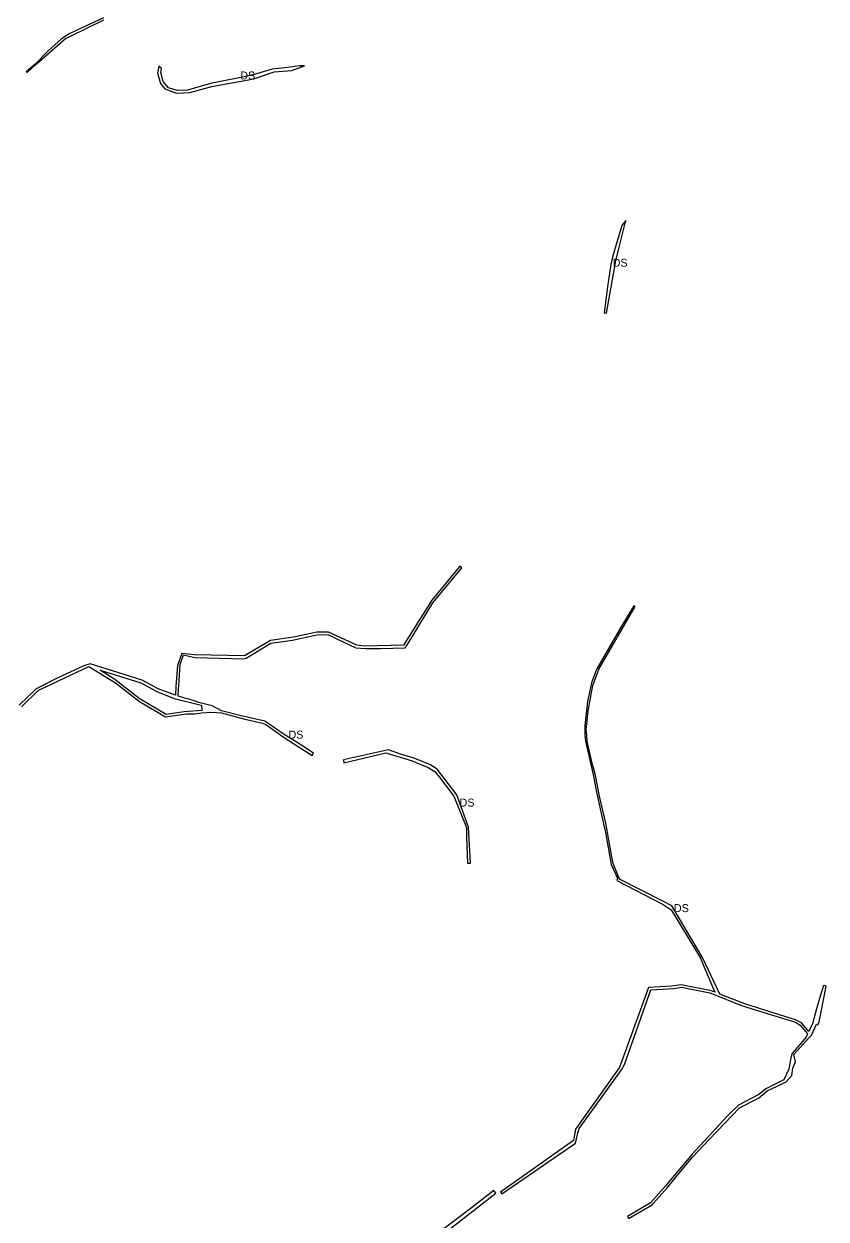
# Model space of a CAD drawing. Extents: x -477304 to -465641, y -1159113 to -1149285.
# Drawn here: x -475036 to -474134, y -1152941 to -1151597 of the extents above; entities that cross this region are included whole.
import ezdxf

# ---------------------------------------------------------------- set-up
doc = ezdxf.new("R2010")
doc.units = 0
doc.layers.add('35', color=7, linetype='Continuous')

msp = doc.modelspace()

# ---------------------------------------------------------------- linework, layer by layer
at = {"layer": '35'}
for p, q in [((-474985.6, -1151608.3), (-474994, -1151613.9)), ((-475023.8, -1151642.3), (-475033.9, -1151651.1)), ((-474881.6, -1151647.1), (-474884.7, -1151644.6)), ((-474882.5, -1151651.8), (-474881.6, -1151647.1)), ((-475033.9, -1151651.1), (-475032.5, -1151651.4)), ((-474757, -1151648), (-474781, -1151655.2)), ((-474878.1, -1151670), (-474864.7, -1151675.1)), ((-474849.7, -1151674.4), (-474825.2, -1151667.5)), ((-474864.7, -1151675.1), (-474849.7, -1151674.4)), ((-474359.3, -1151818.1), (-474363.9, -1151823.9)), ((-474380.1, -1151892.6), (-474383.8, -1151922.1)), ((-474603.8, -1152293.3), (-474576.5, -1152248.2)), ((-474348.7, -1152252.2), (-474350.5, -1152251.4)), ((-474389.6, -1152322.9), (-474348.7, -1152252.2)), ((-474733, -1152286.9), (-474759.2, -1152290.6)), ((-474694.4, -1152283.8), (-474685.9, -1152287.8)), ((-474661.8, -1152295.8), (-474693.8, -1152281.2)), ((-474858.9, -1152305.1), (-474863.5, -1152318.5)), ((-474844.5, -1152306.7), (-474858.9, -1152305.1)), ((-474652.1, -1152299.5), (-474635.2, -1152299.4)), ((-474635.2, -1152299.4), (-474607.5, -1152298.7)), ((-474607.5, -1152298.7), (-474603.8, -1152293.3)), ((-474863.5, -1152318.5), (-474865.4, -1152342.3)), ((-474862.2, -1152341.3), (-474860.6, -1152317.5)), ((-474860.6, -1152317.5), (-474856.8, -1152306.8)), ((-475017.3, -1152345.2), (-474963.5, -1152319.8)), ((-474963.5, -1152319.8), (-474933.5, -1152338.2)), ((-474950.6, -1152323.8), (-474904.8, -1152338.1)), ((-474394.3, -1152328), (-474397.8, -1152338.3)), ((-474396.4, -1152341.3), (-474390.5, -1152325.2)), ((-474393.1, -1152324.6), (-474394.3, -1152328)), ((-474392.1, -1152322.3), (-474393.1, -1152324.6)), ((-474390.5, -1152325.2), (-474389.6, -1152322.9)), ((-475020, -1152346.5), (-475017.3, -1152345.2)), ((-474904.8, -1152338.1), (-474886.8, -1152347.7)), ((-474865.4, -1152342.3), (-474866, -1152352.1)), ((-474863.1, -1152353), (-474862.5, -1152344.7)), ((-474862.5, -1152344.7), (-474862.2, -1152341.3)), ((-474397.8, -1152338.3), (-474402.5, -1152359)), ((-475039.1, -1152365.1), (-475020, -1152346.5)), ((-474886.8, -1152347.7), (-474867.3, -1152355.6)), ((-474867.3, -1152355.6), (-474839.9, -1152362.6)), ((-474847, -1152357.6), (-474863.1, -1152353)), ((-474839.7, -1152360.1), (-474847, -1152357.6)), ((-474402.5, -1152359), (-474405.5, -1152386.1)), ((-474856, -1152370.6), (-474876.6, -1152373.7)), ((-474836.4, -1152369.3), (-474856, -1152370.6)), ((-474841.4, -1152372.6), (-474836.3, -1152371.9)), ((-474839.9, -1152362.6), (-474836.7, -1152363.4)), ((-474824.5, -1152364), (-474839.7, -1152360.1)), ((-474836.7, -1152363.4), (-474836.4, -1152369.3)), ((-474814, -1152369.6), (-474824.5, -1152364)), ((-474792, -1152375.3), (-474814, -1152369.6)), ((-474814, -1152371.8), (-474789.3, -1152378.8)), ((-474765.4, -1152381.2), (-474792, -1152375.3)), ((-474789.3, -1152378.8), (-474768, -1152383.6)), ((-474405.5, -1152386.1), (-474405.6, -1152397.3)), ((-474403.8, -1152390.5), (-474402.7, -1152381.3)), ((-474744.8, -1152398.8), (-474731, -1152407.7)), ((-474405.6, -1152397.3), (-474404.8, -1152403.7)), ((-474403.3, -1152397.2), (-474403.8, -1152390.5)), ((-474731, -1152407.7), (-474712.2, -1152419.8)), ((-474710.8, -1152417.2), (-474716.3, -1152413.6)), ((-474712.2, -1152419.8), (-474710.8, -1152417.2)), ((-474626.3, -1152413.5), (-474677, -1152424.9)), ((-474677, -1152424.9), (-474676.7, -1152428.1)), ((-474676.7, -1152428.1), (-474629.3, -1152416.9)), ((-474629.3, -1152416.9), (-474599.5, -1152425.8)), ((-474611.8, -1152418.8), (-474626.3, -1152413.5)), ((-474599.5, -1152425.8), (-474581.6, -1152433.4)), ((-474581.6, -1152433.4), (-474574.1, -1152437.8)), ((-474574.1, -1152437.8), (-474569.5, -1152443.7)), ((-474549.3, -1152464.1), (-474571.6, -1152435.2)), ((-474569.5, -1152443.7), (-474552.7, -1152465.5)), ((-474552.7, -1152465.5), (-474538.7, -1152500.8)), ((-474392.3, -1152461.2), (-474384.4, -1152496.9)), ((-474384.4, -1152496.9), (-474382.2, -1152506.6)), ((-474374.9, -1152534), (-474381.8, -1152496)), ((-474308.4, -1152593.3), (-474281.1, -1152638.4)), ((-474253.7, -1152688.1), (-474273.1, -1152646.9)), ((-474271.2, -1152657.8), (-474259.3, -1152685.9)), ((-474333.7, -1152680.6), (-474364.6, -1152765.4)), ((-474307.4, -1152679.4), (-474333.7, -1152680.6)), ((-474297, -1152677.9), (-474307.4, -1152679.4)), ((-474137, -1152678.6), (-474141.6, -1152693.1)), ((-474134, -1152679.4), (-474137, -1152678.6)), ((-474361, -1152767.3), (-474331.3, -1152683.3)), ((-474225.4, -1152699.3), (-474253.7, -1152688.1)), ((-474141.6, -1152693.1), (-474144.9, -1152704.8)), ((-474230.2, -1152700.8), (-474210.2, -1152706.9)), ((-474212.2, -1152703.4), (-474225.4, -1152699.3)), ((-474207.8, -1152704.8), (-474212.2, -1152703.4)), ((-474210.2, -1152706.9), (-474168.4, -1152719.8)), ((-474168.3, -1152717.2), (-474207.8, -1152704.8)), ((-474168.4, -1152719.8), (-474163.2, -1152723.1)), ((-474161.7, -1152720.6), (-474168.3, -1152717.2)), ((-474153.6, -1152730.1), (-474161.7, -1152720.6)), ((-474143.5, -1152722.7), (-474142, -1152719.4)), ((-474163.2, -1152723.1), (-474155, -1152733)), ((-474155, -1152733), (-474156.6, -1152736.6)), ((-474156.6, -1152736.6), (-474172.7, -1152755.2)), ((-474170.5, -1152756.3), (-474152.7, -1152736.6)), ((-474174.1, -1152761.7), (-474176, -1152772.8)), ((-474172.7, -1152755.2), (-474174.1, -1152761.7)), ((-474168.6, -1152764.5), (-474170.5, -1152756.3)), ((-474366.9, -1152771.1), (-474415.8, -1152840.2)), ((-474398, -1152820.4), (-474364.3, -1152773.2)), ((-474364.6, -1152765.4), (-474366.9, -1152771.1)), ((-474364.3, -1152773.2), (-474361, -1152767.3)), ((-474172.5, -1152779.7), (-474171.3, -1152771.4)), ((-474171.3, -1152771.4), (-474168.6, -1152764.5)), ((-474189, -1152791.7), (-474178.8, -1152786.7)), ((-474178.8, -1152786.7), (-474172.5, -1152779.7)), ((-474201.9, -1152794.9), (-474209.7, -1152801)), ((-474200.2, -1152796.9), (-474189, -1152791.7)), ((-474265.2, -1152851.2), (-474231.6, -1152816.2)), ((-474411.9, -1152839.5), (-474398, -1152820.4)), ((-474492.8, -1152908.6), (-474415.9, -1152855.7)), ((-474284.7, -1152872), (-474265.2, -1152851.2)), ((-474312.9, -1152905.9), (-474290.3, -1152878.7)), ((-474290.3, -1152878.7), (-474284.7, -1152872)), ((-474314.7, -1152904), (-474331.6, -1152922.8)), ((-474327.8, -1152923), (-474312.9, -1152905.9)), ((-474331.6, -1152922.8), (-474357.3, -1152938.5)), ((-474357.3, -1152938.5), (-474356.2, -1152940.6))]:
    msp.add_line(p, q, dxfattribs=at)
for points in [[(-475032.5, -1151651.4), (-475022.6, -1151642.5), (-474989.5, -1151613.4), (-474984.8, -1151611.2), (-474946.4, -1151592.6)], [(-474947, -1151590.4), (-474979.1, -1151605.2), (-474985.6, -1151608.3)], [(-474994, -1151613.9), (-475009.7, -1151627.6), (-475023.8, -1151642.3)], [(-474884.7, -1151644.6), (-474886.2, -1151652.4), (-474882.8, -1151664.1), (-474878.1, -1151670)], [(-474825.2, -1151667.5), (-474777.9, -1151658.7), (-474754.9, -1151650.8), (-474735.1, -1151649.4), (-474720.9, -1151644.4), (-474726.2, -1151644.2), (-474743.1, -1151646.3), (-474757, -1151648)], [(-474873.8, -1151668.9), (-474879.8, -1151661.9), (-474882.5, -1151651.8)], [(-474781, -1151655.2), (-474826.5, -1151664.2), (-474852.4, -1151671.7), (-474864, -1151671.8), (-474873.8, -1151668.9)], [(-474383.8, -1151922.1), (-474380.9, -1151922.3), (-474370.6, -1151863.7), (-474367.9, -1151852.6), (-474359.3, -1151818.1)], [(-474363.9, -1151823.9), (-474374.1, -1151857.9), (-474376.1, -1151867.6), (-474380.1, -1151892.6)], [(-474576.5, -1152248.2), (-474543.9, -1152208.8), (-474546, -1152207), (-474577.5, -1152245), (-474609.3, -1152295.9), (-474653.6, -1152296.8), (-474661.8, -1152295.8)], [(-474350.5, -1152251.4), (-474364.2, -1152274.4), (-474392.1, -1152322.3)], [(-474759.2, -1152290.6), (-474788.3, -1152307.8), (-474844.5, -1152306.7)], [(-474786.4, -1152310.5), (-474758.6, -1152293.6), (-474734.4, -1152290.1)], [(-474734.4, -1152290.1), (-474706.8, -1152284), (-474694.4, -1152283.8)], [(-474693.8, -1152281.2), (-474706.8, -1152281.2), (-474733, -1152286.9)], [(-474685.9, -1152287.8), (-474683.5, -1152288.9), (-474663.2, -1152298.6), (-474652.1, -1152299.5)], [(-474866, -1152352.1), (-474885.5, -1152344.7), (-474903.4, -1152335.2), (-474962, -1152316.7), (-474969.2, -1152319.1), (-474999, -1152332.9)], [(-474856.8, -1152306.8), (-474844.1, -1152309.5), (-474788.9, -1152311.3), (-474786.4, -1152310.5)], [(-474876.6, -1152373.7), (-474906.7, -1152355.8), (-474934.1, -1152334.4), (-474950.6, -1152323.8)], [(-474999, -1152332.9), (-475022.5, -1152344.9), (-475041.8, -1152363.4)], [(-474933.5, -1152338.2), (-474906.3, -1152359.2), (-474877.1, -1152376.2)], [(-474402.7, -1152381.3), (-474401.7, -1152369.8), (-474396.4, -1152341.3)], [(-474877.1, -1152376.2), (-474853.4, -1152372.9), (-474844.7, -1152373), (-474841.4, -1152372.6)], [(-474836.3, -1152371.9), (-474826.2, -1152371.2), (-474819.7, -1152371.5), (-474814, -1152371.8)], [(-474768, -1152383.6), (-474764.2, -1152385), (-474744.8, -1152398.8)], [(-474716.3, -1152413.6), (-474729.1, -1152405.2), (-474743.6, -1152396.2), (-474765.4, -1152381.2)], [(-474397.3, -1152428.7), (-474402.8, -1152403.7), (-474403.3, -1152397.2)], [(-474404.8, -1152403.7), (-474395.6, -1152443.2), (-474392.3, -1152461.2)], [(-474571.6, -1152435.2), (-474580, -1152430.1), (-474599.8, -1152422.2), (-474611.8, -1152418.8)], [(-474390, -1152460), (-474393.5, -1152442.5), (-474394.8, -1152436.6), (-474397.3, -1152428.7)], [(-474534.1, -1152541.1), (-474536.2, -1152500.5), (-474549.3, -1152464.1)], [(-474381.8, -1152496), (-474388.8, -1152465.5), (-474390, -1152460)], [(-474538.7, -1152500.8), (-474538.4, -1152511.3), (-474537.4, -1152541), (-474534.1, -1152541.1)], [(-474382.2, -1152506.6), (-474375.8, -1152542.3), (-474368.6, -1152557.9)], [(-474366.3, -1152559.1), (-474373.4, -1152541.2), (-474374.9, -1152534)], [(-474368.6, -1152557.9), (-474369.3, -1152560.6), (-474317.5, -1152587.4), (-474308.4, -1152593.3)], [(-474273.1, -1152646.9), (-474279.2, -1152636.8), (-474307.7, -1152589.1), (-474317.7, -1152583.6), (-474366.3, -1152559.1)], [(-474281.1, -1152638.4), (-474275.3, -1152647.9), (-474271.2, -1152657.8)], [(-474331.3, -1152683.3), (-474305.5, -1152682), (-474296.8, -1152680.4)], [(-474259.3, -1152685.9), (-474262.9, -1152684.5), (-474297, -1152677.9)], [(-474296.8, -1152680.4), (-474264.7, -1152686.7), (-474260, -1152688.6), (-474230.2, -1152700.8)], [(-474142, -1152719.4), (-474140.1, -1152710), (-474134, -1152679.4)], [(-474144.9, -1152704.8), (-474149.5, -1152721.5), (-474153.6, -1152730.1)], [(-474152.7, -1152736.6), (-474150.6, -1152734.5), (-474145, -1152722), (-474143.5, -1152722.7)], [(-474176, -1152772.8), (-474181.6, -1152784.5), (-474201.9, -1152794.9)], [(-474209.7, -1152801), (-474232.6, -1152813), (-474244.4, -1152824.9)], [(-474231.6, -1152816.2), (-474210.2, -1152805.1), (-474200.2, -1152796.9)], [(-474244.4, -1152824.9), (-474284.8, -1152868.1), (-474314.7, -1152904)], [(-474415.8, -1152840.2), (-474418.1, -1152852.7), (-474500.3, -1152911)], [(-474415.9, -1152855.7), (-474413.2, -1152844.6), (-474411.9, -1152839.5)], [(-474597, -1152983.2), (-474505.5, -1152911.9), (-474507.8, -1152909.2), (-474536.4, -1152931.1), (-474568.7, -1152955.6)], [(-474500.3, -1152911), (-474498.9, -1152912.8), (-474492.8, -1152908.6)], [(-474356.2, -1152940.6), (-474329.7, -1152925.1), (-474327.8, -1152923)]]:
    msp.add_lwpolyline(points, dxfattribs=at)

# ---------------------------------------------------------------- texts
for p in [(-474793, -1151659.6), (-474374.1, -1151870.2), (-474738.8, -1152400.9), (-474546.3, -1152477.3), (-474305.2, -1152596)]:
    msp.add_text('DS', height=9, dxfattribs=at).set_placement(p)

doc.saveas('drawing.dxf')
